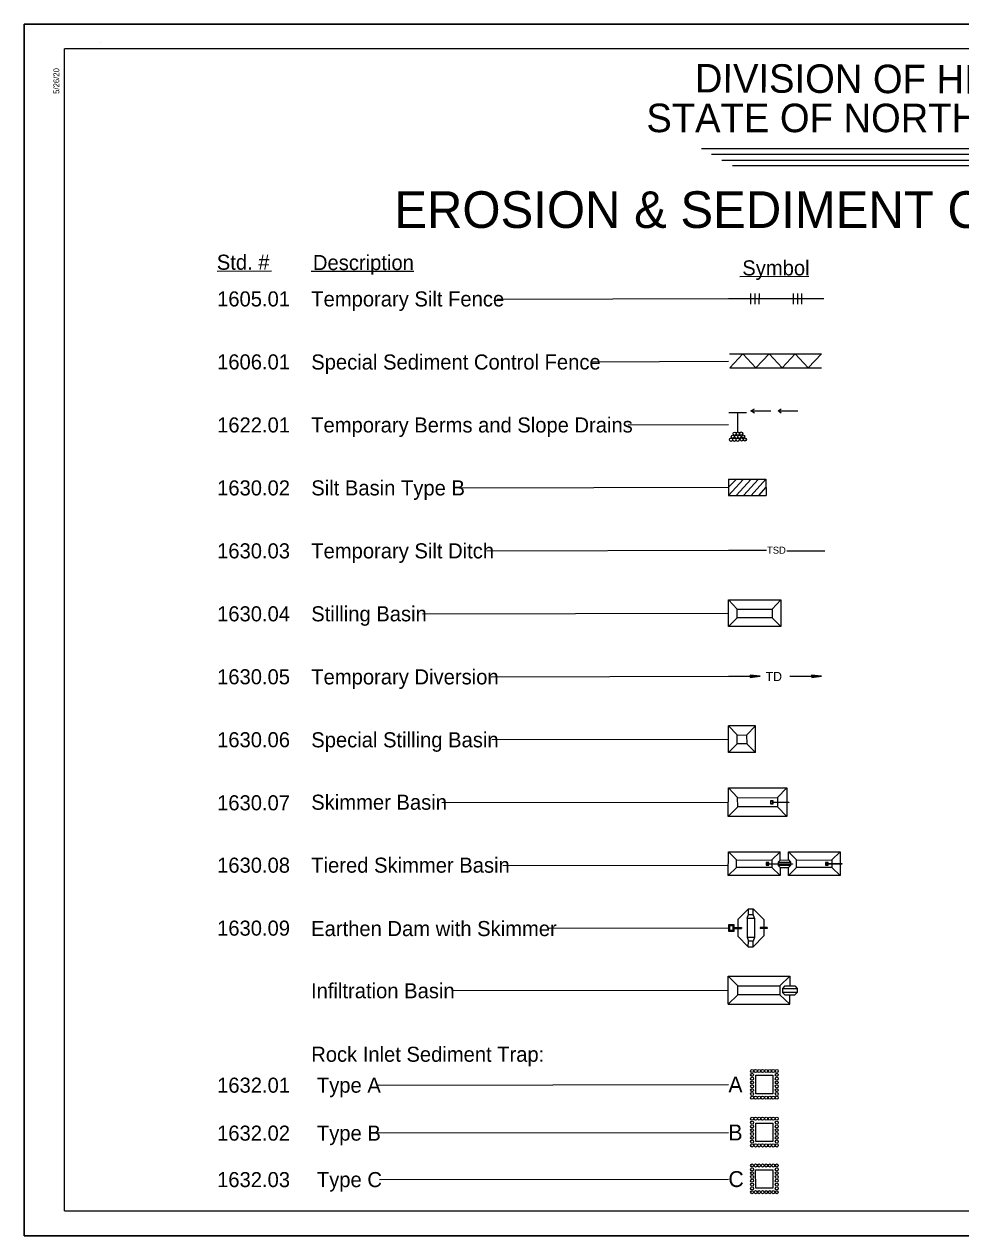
# Model space of a CAD drawing. Extents: x 1677124 to 1678808, y 1331209 to 1332299.
# Drawn here: x 1677124 to 1677966, y 1331209 to 1332299 of the extents above; entities that cross this region are included whole.
import ezdxf

# ---------------------------------------------------------------- set-up
doc = ezdxf.new("R2010")
doc.units = 0
for name, color, linetype in [('Blank Plan Sheet Both CELL', 7, 'Continuous'), ('EC Title Sheet CELL', 7, 'Continuous'), ('Old_Level_1', 7, 'Continuous'), ('Old_Level_12', 7, 'Continuous'), ('Sheet Data Field CELL', 7, 'Continuous'), ('Sheet Plan CELL', 7, 'Continuous'), ('Sheet Plot Border Outside CELL', 7, 'Continuous'), ('z - Construction', 7, 'Continuous')]:
    doc.layers.add(name, color=color, linetype=linetype)

msp = doc.modelspace()

# ---------------------------------------------------------------- linework, layer by layer
at = {"layer": 'Blank Plan Sheet Both CELL'}
msp.add_line((1677192.4, 1332281.7), (1677192.4, 1332281.7), dxfattribs=at)
at = {"layer": 'EC Title Sheet CELL'}
for p, q in [((1677297.5, 1332076.6), (1677346.5, 1332076.7)), ((1677382.1, 1332076.6), (1677474.2, 1332076.6)), ((1677767.2, 1332071.8), (1677829.4, 1332071.9)), ((1677549.2, 1332051.5), (1677757.1, 1332052.1)), ((1677757.1, 1332052.1), (1677842.7, 1332052.1)), ((1677777, 1332056.6), (1677777, 1332047)), ((1677780.9, 1332056.6), (1677780.9, 1332047)), ((1677784.6, 1332056.6), (1677784.5, 1332047)), ((1677815.2, 1332056.6), (1677815.2, 1332047)), ((1677819.1, 1332056.6), (1677819.1, 1332047)), ((1677822.8, 1332056.6), (1677822.8, 1332047)), ((1677633.2, 1331994.9), (1677757.1, 1331995.5)), ((1677758.1, 1332002.2), (1677840.6, 1332002.2)), ((1677758.3, 1331989.6), (1677770.1, 1332002.2)), ((1677770.1, 1332002.2), (1677781.8, 1331989.5)), ((1677781.8, 1331989.5), (1677793.6, 1332002.2)), ((1677793.6, 1332002.2), (1677805.3, 1331989.6)), ((1677805.3, 1331989.6), (1677817, 1332002.2)), ((1677817, 1332002.2), (1677828.8, 1331989.6)), ((1677828.8, 1331989.6), (1677840.6, 1332002.2)), ((1677758.3, 1331989.6), (1677840.6, 1331989.6)), ((1677777.2, 1331950.9), (1677780.4, 1331952.9)), ((1677777.2, 1331950.9), (1677780.4, 1331952.9)), ((1677780.4, 1331948.9), (1677777.2, 1331950.9)), ((1677780.4, 1331948.9), (1677777.2, 1331950.9)), ((1677801.6, 1331950.9), (1677804.5, 1331952.9)), ((1677804.5, 1331948.9), (1677801.6, 1331950.9)), ((1677757.4, 1331949.5), (1677773.3, 1331949.5)), ((1677765.5, 1331932), (1677765.5, 1331949.2)), ((1677666.8, 1331938.3), (1677757.1, 1331938.8)), ((1677770.7, 1331889.6), (1677757.1, 1331874.9)), ((1677757.1, 1331889.6), (1677790.8, 1331889.5)), ((1677757.1, 1331889.6), (1677757.1, 1331874.9)), ((1677763.9, 1331889.3), (1677757.1, 1331882.2)), ((1677777.5, 1331889.5), (1677763.9, 1331874.9)), ((1677784, 1331889.5), (1677770.7, 1331874.9)), ((1677790.8, 1331889.5), (1677777.5, 1331874.9)), ((1677790.8, 1331889.5), (1677790.9, 1331874.9)), ((1677514.9, 1331881.7), (1677757.1, 1331882.2)), ((1677757.1, 1331874.9), (1677790.9, 1331874.9)), ((1677790.8, 1331882.2), (1677784.1, 1331874.9)), ((1677540, 1331825.1), (1677757.1, 1331825.6)), ((1677757.1, 1331825.6), (1677791.2, 1331825.6)), ((1677809.6, 1331825.2), (1677843.7, 1331825.2)), ((1677764.8, 1331772.8), (1677757, 1331781)), ((1677764.8, 1331772.8), (1677757, 1331781)), ((1677757, 1331757), (1677757, 1331781)), ((1677757, 1331757), (1677757, 1331781)), ((1677757, 1331781), (1677804.2, 1331781)), ((1677796.3, 1331772.8), (1677804.2, 1331781)), ((1677804.2, 1331781), (1677804.2, 1331757)), ((1677482, 1331768.6), (1677757, 1331769)), ((1677757, 1331757), (1677764.8, 1331764.9)), ((1677757, 1331757), (1677764.8, 1331764.9)), ((1677781.3, 1331757), (1677757, 1331757)), ((1677804.2, 1331757), (1677757, 1331757)), ((1677796.3, 1331764.9), (1677804.2, 1331757)), ((1677543.9, 1331711.8), (1677757.1, 1331712.4)), ((1677757.1, 1331712.4), (1677785.6, 1331712.4)), ((1677785.6, 1331712.4), (1677776.7, 1331713.2)), ((1677776.7, 1331713.2), (1677776.7, 1331711.2)), ((1677776.7, 1331711.2), (1677785.6, 1331712.4)), ((1677812.1, 1331712.4), (1677840.6, 1331712.4)), ((1677840.6, 1331712.4), (1677831.7, 1331713.2)), ((1677831.7, 1331713.2), (1677831.9, 1331711.2)), ((1677831.9, 1331711.2), (1677840.6, 1331712.4)), ((1677757, 1331643.8), (1677757, 1331667.7)), ((1677781.3, 1331667.7), (1677757, 1331667.7)), ((1677764.8, 1331659.6), (1677757, 1331667.7)), ((1677773.4, 1331659.5), (1677781.3, 1331667.7)), ((1677781.3, 1331643.8), (1677781.3, 1331667.7)), ((1677544.4, 1331655.5), (1677757, 1331655.7)), ((1677757, 1331643.8), (1677764.8, 1331651.7)), ((1677773.5, 1331651.7), (1677781.3, 1331643.8)), ((1677781.3, 1331643.8), (1677757, 1331643.8)), ((1677756.9, 1331586.2), (1677757, 1331612)), ((1677765.3, 1331603.2), (1677757, 1331612)), ((1677757, 1331612), (1677783.2, 1331612)), ((1677765.4, 1331594.8), (1677765.3, 1331603.2)), ((1677765.3, 1331603.2), (1677801.1, 1331603.1)), ((1677783.2, 1331612), (1677809.4, 1331612)), ((1677801.1, 1331603.2), (1677809.4, 1331612)), ((1677801.1, 1331603.1), (1677801.1, 1331594.8)), ((1677809.4, 1331612), (1677809.5, 1331586.2)), ((1677499.4, 1331598.8), (1677757, 1331599.1)), ((1677756.9, 1331586.2), (1677765.4, 1331594.8)), ((1677801.1, 1331594.8), (1677765.4, 1331594.8)), ((1677797.3, 1331600.4), (1677794.8, 1331600.4)), ((1677794.8, 1331600.4), (1677794.8, 1331597.5)), ((1677794.8, 1331597.5), (1677797.3, 1331597.5)), ((1677796.9, 1331599.9), (1677795.2, 1331599.9)), ((1677795.2, 1331599.9), (1677795.2, 1331598)), ((1677795.2, 1331598), (1677796.9, 1331598)), ((1677796.9, 1331598), (1677796.9, 1331599.9)), ((1677797.3, 1331597.5), (1677797.3, 1331600.4)), ((1677797.3, 1331599.2), (1677811.2, 1331599.1)), ((1677811.2, 1331598.7), (1677797.3, 1331598.7)), ((1677801.1, 1331594.8), (1677809.5, 1331586.2)), ((1677811.2, 1331599.1), (1677811.2, 1331598.7)), ((1677783.2, 1331586.2), (1677756.9, 1331586.2)), ((1677809.5, 1331586.2), (1677783.2, 1331586.2)), ((1677756.9, 1331533.3), (1677757, 1331554.5)), ((1677764.4, 1331547.2), (1677757, 1331554.5)), ((1677757, 1331554.5), (1677780.2, 1331554.5)), ((1677780.2, 1331554.5), (1677803.4, 1331554.5)), ((1677796.1, 1331547.2), (1677803.4, 1331554.5)), ((1677803.4, 1331547.1), (1677803.4, 1331554.5)), ((1677818.3, 1331547.2), (1677810.9, 1331554.5)), ((1677810.9, 1331554.5), (1677834.1, 1331554.5)), ((1677810.9, 1331547.2), (1677810.9, 1331554.5)), ((1677834.1, 1331554.5), (1677857.4, 1331554.5)), ((1677850, 1331547.2), (1677857.4, 1331554.5)), ((1677857.4, 1331554.5), (1677857.4, 1331533.3)), ((1677554.3, 1331542.2), (1677757, 1331542.5)), ((1677756.9, 1331533.3), (1677764.4, 1331540.3)), ((1677764.4, 1331540.3), (1677764.4, 1331547.2)), ((1677764.4, 1331547.2), (1677796, 1331547.1)), ((1677796, 1331540.3), (1677764.4, 1331540.3)), ((1677793.4, 1331544.8), (1677791.1, 1331544.8)), ((1677791.1, 1331544.8), (1677791.1, 1331542.4)), ((1677791.1, 1331542.4), (1677793.4, 1331542.4)), ((1677793, 1331544.4), (1677791.5, 1331544.4)), ((1677791.5, 1331544.4), (1677791.5, 1331542.8)), ((1677791.5, 1331542.8), (1677793, 1331542.8)), ((1677793, 1331542.8), (1677793, 1331544.4)), ((1677793.4, 1331542.4), (1677793.4, 1331544.8)), ((1677793.4, 1331543.8), (1677814.5, 1331543.8)), ((1677814.5, 1331543.4), (1677793.4, 1331543.4)), ((1677796, 1331547.1), (1677796, 1331540.3)), ((1677796, 1331540.3), (1677803.5, 1331533.3)), ((1677803.4, 1331547.1), (1677801.6, 1331545.2)), ((1677801.6, 1331545.2), (1677812.8, 1331545.3)), ((1677801.6, 1331545.2), (1677801.6, 1331542.2)), ((1677803.4, 1331540.3), (1677801.6, 1331542.2)), ((1677812.8, 1331542.2), (1677801.6, 1331542.2)), ((1677803.4, 1331547.1), (1677810.9, 1331547.2)), ((1677803.4, 1331540.3), (1677803.5, 1331533.3)), ((1677803.4, 1331540.3), (1677810.9, 1331540.3)), ((1677810.9, 1331547.2), (1677812.8, 1331545.3)), ((1677810.9, 1331540.3), (1677812.8, 1331542.2)), ((1677810.9, 1331533.3), (1677818.3, 1331540.3)), ((1677810.9, 1331533.3), (1677810.9, 1331540.3)), ((1677812.8, 1331545.3), (1677812.8, 1331542.2)), ((1677814.5, 1331543.8), (1677814.5, 1331543.4)), ((1677818.3, 1331540.3), (1677818.3, 1331547.2)), ((1677818.3, 1331547.2), (1677850, 1331547.1)), ((1677850, 1331540.3), (1677818.3, 1331540.3)), ((1677846.6, 1331544.9), (1677844.4, 1331544.9)), ((1677844.4, 1331544.9), (1677844.4, 1331542.5)), ((1677844.4, 1331542.5), (1677846.6, 1331542.5)), ((1677846.2, 1331544.5), (1677844.8, 1331544.5)), ((1677844.8, 1331544.5), (1677844.8, 1331542.9)), ((1677844.8, 1331542.9), (1677846.2, 1331542.9)), ((1677846.2, 1331542.9), (1677846.2, 1331544.5)), ((1677846.6, 1331542.5), (1677846.6, 1331544.9)), ((1677846.6, 1331543.9), (1677858.9, 1331543.9)), ((1677858.9, 1331543.5), (1677846.6, 1331543.5)), ((1677850, 1331547.1), (1677850, 1331540.3)), ((1677850, 1331540.3), (1677857.4, 1331533.3)), ((1677858.9, 1331543.9), (1677858.9, 1331543.5)), ((1677780.2, 1331533.3), (1677756.9, 1331533.3)), ((1677803.5, 1331533.2), (1677780.2, 1331533.3)), ((1677834.2, 1331533.3), (1677810.9, 1331533.3)), ((1677857.4, 1331533.2), (1677834.2, 1331533.3)), ((1677775, 1331503.1), (1677765.5, 1331493.5)), ((1677765.5, 1331493.5), (1677765.6, 1331486.5)), ((1677774, 1331494.7), (1677775, 1331498)), ((1677774, 1331494.7), (1677774, 1331477.7)), ((1677774, 1331494.7), (1677780.4, 1331494.7)), ((1677775, 1331503.1), (1677779.3, 1331503.1)), ((1677775, 1331498), (1677775, 1331503.1)), ((1677775, 1331498), (1677779.2, 1331498)), ((1677779.2, 1331498), (1677779.3, 1331503.1)), ((1677780.4, 1331494.7), (1677779.2, 1331498)), ((1677779.3, 1331503.1), (1677788.8, 1331493.5)), ((1677780.4, 1331494.7), (1677780.5, 1331477.7)), ((1677788.8, 1331493.5), (1677788.8, 1331486.4)), ((1677595.8, 1331485.8), (1677757, 1331486)), ((1677762.3, 1331488.9), (1677757, 1331488.9)), ((1677757, 1331488.9), (1677757, 1331483.1)), ((1677757, 1331483.1), (1677762.3, 1331483.1)), ((1677761.4, 1331488), (1677757.9, 1331488)), ((1677757.9, 1331488), (1677757.9, 1331484.1)), ((1677757.9, 1331484.1), (1677761.4, 1331484.1)), ((1677761.4, 1331484.1), (1677761.4, 1331488)), ((1677762.3, 1331483.1), (1677762.3, 1331488.9)), ((1677762.3, 1331486.5), (1677768.9, 1331486.5)), ((1677762.3, 1331485.5), (1677768.9, 1331485.5)), ((1677765.6, 1331485.5), (1677765.6, 1331478.6)), ((1677768.9, 1331486.5), (1677768.9, 1331485.5)), ((1677791.9, 1331486.4), (1677785.5, 1331486.4)), ((1677785.5, 1331486.4), (1677785.5, 1331485.5)), ((1677791.9, 1331485.5), (1677785.5, 1331485.5)), ((1677788.8, 1331485.5), (1677788.9, 1331479)), ((1677791.9, 1331486.4), (1677791.9, 1331485.5)), ((1677765.6, 1331478.6), (1677774.9, 1331469.2)), ((1677774, 1331477.7), (1677775, 1331474.3)), ((1677780.5, 1331477.6), (1677774, 1331477.6)), ((1677774.9, 1331469.2), (1677775, 1331474.3)), ((1677779.2, 1331474.3), (1677775, 1331474.3)), ((1677788.9, 1331479), (1677779.2, 1331469.2)), ((1677780.5, 1331477.6), (1677779.2, 1331474.3)), ((1677779.2, 1331469.2), (1677779.2, 1331474.3)), ((1677774.9, 1331469.2), (1677779.2, 1331469.2)), ((1677756.7, 1331417.4), (1677756.8, 1331442.7)), ((1677765.6, 1331434), (1677756.8, 1331442.7)), ((1677756.8, 1331442.7), (1677784.5, 1331442.7)), ((1677784.5, 1331442.7), (1677812.2, 1331442.7)), ((1677803.3, 1331434), (1677812.2, 1331442.7)), ((1677812.2, 1331442.7), (1677812.2, 1331434)), ((1677509.5, 1331429.8), (1677756.8, 1331430.1)), ((1677765.6, 1331425.8), (1677765.6, 1331434)), ((1677765.6, 1331434), (1677803.3, 1331434)), ((1677803.3, 1331434), (1677803.3, 1331425.8)), ((1677807.7, 1331433.9), (1677805.5, 1331431.7)), ((1677805.5, 1331431.7), (1677818.8, 1331431.7)), ((1677805.5, 1331431.7), (1677805.5, 1331428)), ((1677807.7, 1331425.8), (1677805.5, 1331428)), ((1677818.8, 1331428), (1677805.5, 1331428)), ((1677807.7, 1331433.9), (1677816.6, 1331434)), ((1677816.6, 1331434), (1677818.8, 1331431.7)), ((1677816.6, 1331425.8), (1677818.8, 1331428)), ((1677818.8, 1331431.7), (1677818.8, 1331428)), ((1677756.7, 1331417.4), (1677765.6, 1331425.8)), ((1677756.7, 1331417.4), (1677812.2, 1331417.4)), ((1677803.3, 1331425.8), (1677765.6, 1331425.8)), ((1677803.3, 1331425.8), (1677812.2, 1331417.4)), ((1677807.7, 1331425.8), (1677816.6, 1331425.8)), ((1677812.2, 1331417.4), (1677812.2, 1331425.8)), ((1677441.4, 1331344.8), (1677757, 1331345.2)), ((1677441.3, 1331301.7), (1677757, 1331302.1)), ((1677443.4, 1331259.9), (1677757, 1331260.3))]:
    msp.add_line(p, q, dxfattribs=at)
for points in [[(1677777.2, 1331950.9), (1677795.1, 1331950.9)], [(1677777.2, 1331950.9), (1677795.1, 1331950.9)], [(1677801.6, 1331950.9), (1677819.4, 1331950.9)]]:
    msp.add_lwpolyline(points, dxfattribs=at)
for points in [[(1677764.8, 1331764.9), (1677764.8, 1331772.8), (1677796.3, 1331772.8), (1677796.3, 1331764.9)], [(1677764.8, 1331651.7), (1677764.8, 1331659.6), (1677773.4, 1331659.5), (1677773.5, 1331651.7)], [(1677781.6, 1331353.6), (1677797, 1331353.6), (1677797, 1331336.9), (1677781.8, 1331336.9)], [(1677781.6, 1331310.5), (1677797, 1331310.5), (1677797, 1331294.1), (1677781.8, 1331293.9)], [(1677781.5, 1331268.7), (1677797, 1331268.7), (1677797, 1331252), (1677781.8, 1331252)]]:
    msp.add_lwpolyline(points, close=True, dxfattribs=at)
for centre, major_axis in [((1677761, 1331927.7), (0, 1.47)), ((1677762.7, 1331930.4), (0, 1.47)), ((1677764.1, 1331927.7), (0, 1.47)), ((1677765.5, 1331930.5), (0, 1.47)), ((1677766.9, 1331927.7), (0, 1.47)), ((1677768.5, 1331930.5), (0, 1.47)), ((1677770.3, 1331927.9), (0, 1.47)), ((1677759.3, 1331925), (0, 1.47)), ((1677762.4, 1331925), (0, 1.47)), ((1677765.4, 1331925), (0, 1.47)), ((1677768.9, 1331925.2), (0, 1.47)), ((1677771.8, 1331925.2), (0, 1.47)), ((1677778.3, 1331357.4), (0, -1.41)), ((1677778.3, 1331354), (0, -1.41)), ((1677778.3, 1331350.5), (0, -1.41)), ((1677781.5, 1331357.4), (0, -1.41)), ((1677784.6, 1331357.4), (0, -1.41)), ((1677787.8, 1331357.4), (0, -1.41)), ((1677791, 1331357.4), (0, -1.41)), ((1677794.2, 1331357.4), (0, -1.41)), ((1677797.4, 1331357.4), (0, -1.41)), ((1677800.5, 1331357.4), (0, -1.41)), ((1677800.5, 1331354), (0, -1.41)), ((1677800.5, 1331350.5), (0, -1.41)), ((1677778.3, 1331347.1), (0, -1.41)), ((1677778.3, 1331343.7), (0, -1.41)), ((1677778.3, 1331340.2), (0, -1.41)), ((1677800.5, 1331347.1), (0, -1.41)), ((1677800.5, 1331343.7), (0, -1.41)), ((1677800.5, 1331340.2), (0, -1.41)), ((1677778.3, 1331336.8), (0, -1.41)), ((1677778.3, 1331333.4), (0, -1.41)), ((1677781.5, 1331333.4), (0, -1.41)), ((1677784.6, 1331333.4), (0, -1.41)), ((1677787.8, 1331333.4), (0, -1.41)), ((1677791, 1331333.4), (0, -1.41)), ((1677794.2, 1331333.4), (0, -1.41)), ((1677797.4, 1331333.4), (0, -1.41)), ((1677800.5, 1331336.8), (0, -1.41)), ((1677800.5, 1331333.4), (0, -1.41)), ((1677778.3, 1331314.5), (0, -1.41)), ((1677778.3, 1331311), (0, -1.41)), ((1677778.3, 1331307.6), (0, -1.41)), ((1677781.5, 1331314.5), (0, -1.41)), ((1677784.7, 1331314.5), (0, -1.41)), ((1677787.8, 1331314.5), (0, -1.41)), ((1677791, 1331314.5), (0, -1.41)), ((1677794.2, 1331314.5), (0, -1.41)), ((1677797.4, 1331314.5), (0, -1.41)), ((1677800.5, 1331314.5), (0, -1.41)), ((1677800.5, 1331311), (0, -1.41)), ((1677800.5, 1331307.6), (0, -1.41)), ((1677778.3, 1331304.2), (0, -1.41)), ((1677778.3, 1331300.8), (0, -1.41)), ((1677778.3, 1331297.3), (0, -1.41)), ((1677800.5, 1331304.2), (0, -1.41)), ((1677800.5, 1331300.8), (0, -1.41)), ((1677800.5, 1331297.3), (0, -1.41)), ((1677778.3, 1331293.9), (0, -1.41)), ((1677778.3, 1331290.5), (0, -1.41)), ((1677781.5, 1331290.5), (0, -1.41)), ((1677784.7, 1331290.5), (0, -1.41)), ((1677787.8, 1331290.5), (0, -1.41)), ((1677791, 1331290.5), (0, -1.41)), ((1677794.2, 1331290.5), (0, -1.41)), ((1677797.4, 1331290.5), (0, -1.41)), ((1677800.5, 1331293.9), (0, -1.41)), ((1677800.5, 1331290.5), (0, -1.41)), ((1677778.3, 1331272.5), (0, -1.41)), ((1677778.3, 1331269), (0, -1.41)), ((1677778.3, 1331265.6), (0, -1.41)), ((1677781.5, 1331272.5), (0, -1.41)), ((1677784.6, 1331272.5), (0, -1.41)), ((1677787.8, 1331272.5), (0, -1.41)), ((1677791, 1331272.5), (0, -1.41)), ((1677794.2, 1331272.5), (0, -1.41)), ((1677797.4, 1331272.5), (0, -1.41)), ((1677800.5, 1331272.5), (0, -1.41)), ((1677800.5, 1331269), (0, -1.41)), ((1677800.5, 1331265.6), (0, -1.41)), ((1677778.3, 1331262.2), (0, -1.41)), ((1677778.3, 1331258.8), (0, -1.41)), ((1677778.3, 1331255.3), (0, -1.41)), ((1677778.3, 1331251.9), (0, -1.41)), ((1677800.5, 1331262.2), (0, -1.41)), ((1677800.5, 1331258.8), (0, -1.41)), ((1677800.5, 1331255.3), (0, -1.41)), ((1677800.5, 1331251.9), (0, -1.41)), ((1677778.3, 1331248.5), (0, -1.41)), ((1677781.5, 1331248.5), (0, -1.41)), ((1677784.6, 1331248.5), (0, -1.41)), ((1677787.8, 1331248.5), (0, -1.41)), ((1677791, 1331248.5), (0, -1.41)), ((1677794.2, 1331248.5), (0, -1.41)), ((1677797.4, 1331248.5), (0, -1.41)), ((1677800.5, 1331248.5), (0, -1.41))]:
    msp.add_ellipse(centre, major_axis=major_axis, ratio=0.927398, dxfattribs=at)
at = {"layer": 'Old_Level_1'}
for p, q in [((1677732.7, 1332186.8), (1678153.9, 1332186.8)), ((1677741.9, 1332181.7), (1678144.3, 1332181.7)), ((1677751.2, 1332176.3), (1678134.6, 1332176.3)), ((1677760.8, 1332171.4), (1678125, 1332171.4))]:
    msp.add_line(p, q, dxfattribs=at)
at = {"layer": 'Sheet Data Field CELL'}
msp.add_line((1677124.1, 1331209.3), (1677124.1, 1331209.3), dxfattribs=at)
at = {"layer": 'Sheet Plan CELL'}
for p, q in [((1677160.2, 1331231.6), (1677160.3, 1332276.3)), ((1678794.2, 1332276.3), (1677160.3, 1332276.3)), ((1677160.2, 1331231.6), (1678794.2, 1331231.6)), ((1677189.9, 1331231.6), (1677189.9, 1331231.6))]:
    msp.add_line(p, q, dxfattribs=at)
at = {"layer": 'Sheet Plot Border Outside CELL'}
msp.add_lwpolyline([(1677124.1, 1332298.6), (1678807.6, 1332298.6), (1678807.6, 1331209.3), (1677124.1, 1331209.3)], close=True, dxfattribs=at)
at = {"layer": 'z - Construction'}
for p, q in [((1678807.6, 1332298.6), (1677124.1, 1332298.6)), ((1677124.1, 1332298.6), (1677124.1, 1331209.3)), ((1677124.1, 1331209.3), (1678807.6, 1331209.3))]:
    msp.add_line(p, q, dxfattribs=at)

# ---------------------------------------------------------------- texts
at = {"layer": 'EC Title Sheet CELL'}
for s, height, p in [('Std. #', 13.57, (1677297.2, 1332077.8)), ('Description', 13.565, (1677383.6, 1332077.5)), ('Symbol', 13.57, (1677769.5, 1332072.7)), ('1605.01', 13.55, (1677297.5, 1332044.8)), ('Temporary Silt Fence', 13.565, (1677382.1, 1332044.8)), ('1606.01', 13.55, (1677297.5, 1331988.2)), ('Special Sediment Control Fence', 13.565, (1677382.1, 1331988.1)), ('1622.01', 13.55, (1677297.5, 1331931.5)), ('Temporary Berms and Slope Drains ', 13.546, (1677382.1, 1331931.5)), ('1630.02', 13.55, (1677297.5, 1331874.9)), ('Silt Basin Type B', 13.565, (1677382.1, 1331874.9)), ('1630.03', 13.55, (1677297.5, 1331818.3)), ('Temporary Silt Ditch', 13.565, (1677382.1, 1331818.3)), ('TSD', 6.34, (1677791.7, 1331822.5)), ('1630.04', 13.55, (1677297.5, 1331761.7)), ('Stilling Basin', 13.565, (1677382.1, 1331761.7)), ('1630.05', 13.55, (1677297.5, 1331705.1)), ('Temporary Diversion', 13.571, (1677382.1, 1331705)), ('TD', 8.23, (1677790.5, 1331708)), ('1630.06', 13.55, (1677297.5, 1331648.5)), ('Special Stilling Basin', 13.565, (1677382.1, 1331648.4)), ('1630.07', 13.55, (1677297.5, 1331591.8)), ('Skimmer Basin', 13.565, (1677382.1, 1331592.3)), ('1630.08', 13.55, (1677297.5, 1331535.7)), ('Tiered Skimmer Basin', 13.565, (1677382.1, 1331535.7)), ('Earthen Dam with Skimmer', 13.565, (1677382, 1331478.7)), ('1630.09', 13.55, (1677297.5, 1331479.1)), ('Infiltration Basin', 13.565, (1677381.9, 1331422.8)), ('Rock Inlet Sediment Trap:', 13.546, (1677382.1, 1331365.7)), ('1632.01', 13.55, (1677297.5, 1331337.9)), (' Type A', 13.57, (1677382.1, 1331337.9)), ('A', 14.3, (1677757, 1331338.1)), ('1632.02', 13.55, (1677297.5, 1331294.8)), (' Type B', 13.57, (1677382.1, 1331294.8)), ('B', 14.3, (1677757, 1331295)), ('1632.03', 13.55, (1677297.5, 1331253)), (' Type C', 13.57, (1677382.1, 1331253)), ('C', 14.3, (1677757, 1331253.1))]:
    msp.add_text(s, height=height, dxfattribs=at).set_placement(p)
at = {"layer": 'Old_Level_1'}
for s, height, p in [('STATE OF NORTH CAROLINA', 25.639, (1677683.3, 1332201.5)), ('EROSION & SEDIMENT CONTROL LEGEND', 32.964, (1677456.7, 1332115.4))]:
    msp.add_text(s, height=height, rotation=360, dxfattribs=at).set_placement(p)
at = {"layer": 'Old_Level_12'}
msp.add_text(' DIVISION OF HIGHWAYS', height=25.639, rotation=359.7699, dxfattribs=at).set_placement((1677717.3, 1332237.3))
at = {"layer": 'Sheet Plan CELL'}
msp.add_text('5/26/20', height=5.2, rotation=90, dxfattribs=at).set_placement((1677155.6, 1332235.9))

doc.saveas('drawing.dxf')
